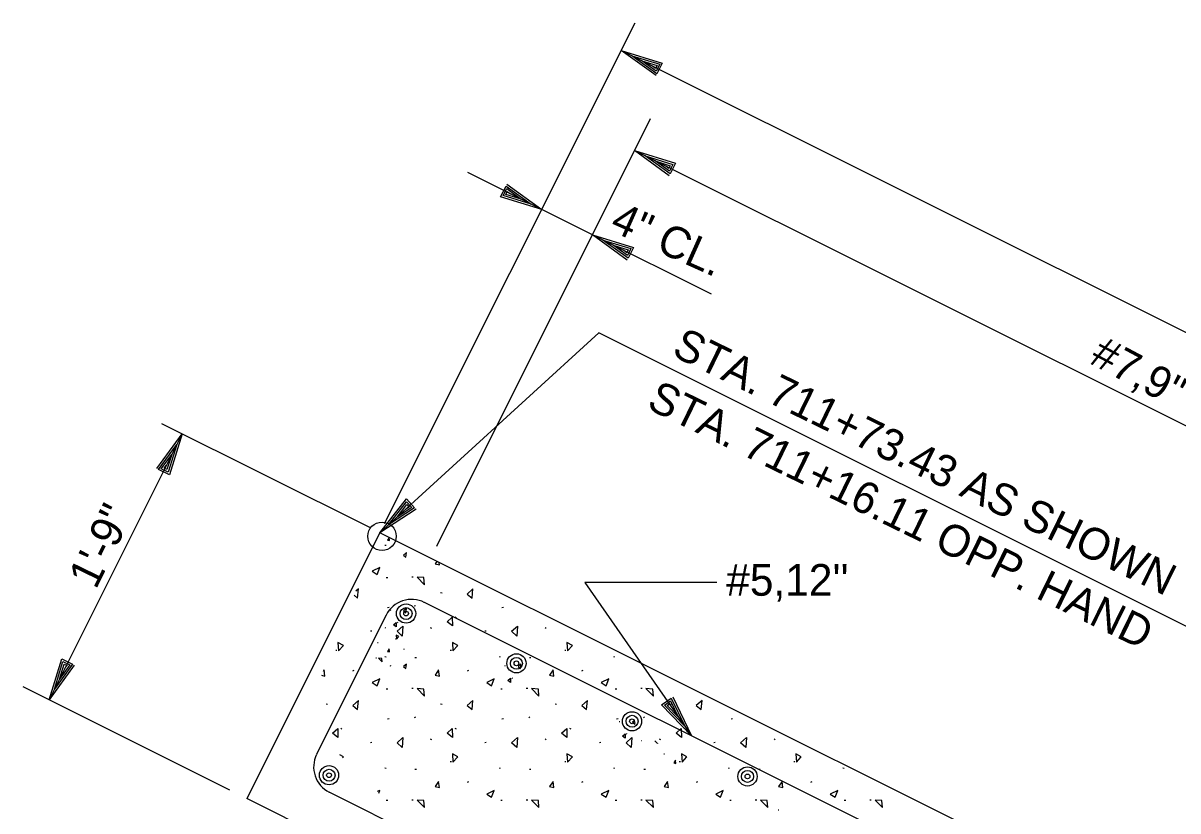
# Model space of a CAD drawing. Extents: x 6 to 106, y 3 to 74.
# Drawn here: x 75.56 to 89.14, y 35.93 to 45.2 of the extents above; entities that cross this region are included whole.
import ezdxf

# ---------------------------------------------------------------- set-up
doc = ezdxf.new("R2010")
doc.units = 0
for name, color, linetype in [('Level 22', 7, 'Continuous'), ('Level 3', 7, 'Continuous'), ('Level 44', 7, 'Continuous'), ('Level 50', 7, 'Continuous')]:
    doc.layers.add(name, color=color, linetype=linetype)

msp = doc.modelspace()

# ---------------------------------------------------------------- linework, layer by layer
at = {"layer": 'Level 22'}
for p, q in [((82.752, 45.203), (79.804, 39.308)), ((95.793, 38.28), (82.591, 44.881)), ((82.933, 44.075), (80.418, 39.043)), ((94.822, 37.665), (82.747, 43.702)), ((81.655, 43.009), (80.788, 43.443)), ((82.252, 42.711), (81.655, 43.009)), ((83.654, 42.01), (82.252, 42.711)), ((90.1, 37.67), (82.326, 41.557)), ((79.648, 39.257), (77.188, 40.487)), ((77.426, 40.368), (75.861, 37.237)), ((79.753, 39.204), (78.188, 36.074)), ((92.955, 32.603), (79.753, 39.204)), ((94.265, 31.389), (80.275, 38.384)), ((79.827, 38.235), (79.007, 36.596)), ((77.986, 36.175), (75.556, 37.39)), ((90.607, 30.423), (79.157, 36.148)), ((88.991, 30.672), (78.188, 36.074))]:
    msp.add_line(p, q, dxfattribs=at)
for centre, start, end in [((80.125, 38.086), 63.4343, 153.4357), ((79.306, 36.446), 153.4355, 243.4349)]:
    msp.add_arc(centre, 0.333, start, end, dxfattribs=at)
at = {"layer": 'Level 3'}
for p, q in [((83.337, 36.928), (83.337, 36.928)), ((83.416, 36.814), (83.416, 36.814))]:
    msp.add_line(p, q, dxfattribs=at)
for points in [[(83.715, 38.616), (82.163, 38.616), (83.416, 36.814)], [(83.199, 37.27), (83.416, 36.814), (83.063, 37.176), (83.18, 37.257), (83.337, 36.928), (83.098, 37.174), (83.172, 37.225), (83.261, 37.037), (83.132, 37.171), (83.162, 37.193), (83.182, 37.151)]]:
    msp.add_lwpolyline(points, dxfattribs=at)
at = {"layer": 'Level 44'}
for p, q in [((82.326, 41.557), (79.753, 39.204)), ((79.824, 39.052), (79.811, 39.054)), ((79.845, 38.674), (79.827, 38.674)), ((80.144, 38.68), (80.127, 38.68)), ((80.483, 38.494), (80.466, 38.497)), ((79.86, 38.325), (79.842, 38.32)), ((80.17, 38.343), (80.157, 38.338)), ((81.206, 38.325), (81.188, 38.32)), ((79.883, 38.289), (79.874, 38.291)), ((80.653, 38.201), (80.638, 38.21)), ((79.656, 38.045), (79.641, 38.044)), ((79.822, 38.081), (79.815, 38.084)), ((79.967, 38.143), (79.96, 38.148)), ((80.363, 38.077), (80.348, 38.084)), ((81.002, 38.045), (80.988, 38.044)), ((81.709, 38.077), (81.695, 38.084)), ((79.732, 37.907), (79.723, 37.907)), ((79.937, 37.952), (79.931, 37.952)), ((79.246, 37.818), (79.233, 37.819)), ((80.038, 37.834), (80.03, 37.83)), ((80.593, 37.818), (80.58, 37.819)), ((81.94, 37.818), (81.926, 37.819)), ((79.713, 37.727), (79.704, 37.727)), ((79.824, 37.74), (79.811, 37.743)), ((79.883, 37.633), (79.874, 37.635)), ((80.183, 37.729), (80.165, 37.729)), ((81.171, 37.74), (81.157, 37.743)), ((81.229, 37.633), (81.221, 37.635)), ((81.529, 37.729), (81.511, 37.729)), ((82.517, 37.74), (82.504, 37.743)), ((79.447, 37.583), (79.431, 37.575)), ((80.793, 37.583), (80.777, 37.575)), ((81.314, 37.487), (81.307, 37.492)), ((82.14, 37.583), (82.124, 37.575)), ((79.845, 37.362), (79.827, 37.362)), ((80.144, 37.368), (80.127, 37.368)), ((81.192, 37.362), (81.174, 37.362)), ((81.491, 37.368), (81.474, 37.368)), ((82.539, 37.362), (82.521, 37.362)), ((82.837, 37.368), (82.82, 37.368)), ((79.137, 37.182), (79.119, 37.185)), ((80.483, 37.182), (80.466, 37.185)), ((81.83, 37.182), (81.813, 37.185)), ((83.177, 37.182), (83.159, 37.185)), ((79.86, 37.013), (79.842, 37.008)), ((80.17, 37.031), (80.157, 37.026)), ((81.206, 37.013), (81.188, 37.008)), ((81.517, 37.031), (81.504, 37.026)), ((82.553, 37.013), (82.535, 37.008)), ((82.576, 36.978), (82.567, 36.979)), ((82.864, 37.031), (82.851, 37.026)), ((83.9, 37.013), (83.882, 37.008)), ((79.306, 36.89), (79.291, 36.899)), ((80.653, 36.89), (80.638, 36.899)), ((82, 36.89), (81.985, 36.899)), ((82.661, 36.831), (82.653, 36.836)), ((83.346, 36.89), (83.331, 36.899)), ((79.656, 36.734), (79.641, 36.732)), ((80.363, 36.766), (80.348, 36.772)), ((81.002, 36.734), (80.988, 36.732)), ((81.709, 36.766), (81.695, 36.772)), ((82.349, 36.734), (82.334, 36.732)), ((82.835, 36.753), (82.828, 36.753)), ((83.056, 36.766), (83.042, 36.772)), ((83.696, 36.734), (83.681, 36.732)), ((84.403, 36.766), (84.388, 36.772)), ((83.099, 36.595), (83.09, 36.595)), ((79.824, 36.429), (79.811, 36.431)), ((80.183, 36.417), (80.165, 36.417)), ((80.593, 36.507), (80.58, 36.508)), ((81.171, 36.429), (81.157, 36.431)), ((81.529, 36.417), (81.511, 36.417)), ((81.94, 36.507), (81.926, 36.508)), ((82.517, 36.429), (82.504, 36.431)), ((82.876, 36.417), (82.858, 36.417)), ((83.286, 36.507), (83.273, 36.508)), ((83.864, 36.429), (83.851, 36.431)), ((84.223, 36.417), (84.205, 36.417)), ((84.633, 36.507), (84.62, 36.508)), ((85.211, 36.429), (85.197, 36.431)), ((80.793, 36.272), (80.777, 36.264)), ((82.14, 36.272), (82.124, 36.264)), ((83.487, 36.272), (83.471, 36.264)), ((84.833, 36.272), (84.817, 36.264)), ((79.845, 36.05), (79.827, 36.05)), ((80.144, 36.057), (80.127, 36.057)), ((81.192, 36.05), (81.174, 36.05)), ((81.491, 36.057), (81.474, 36.057)), ((82.539, 36.05), (82.521, 36.05)), ((82.837, 36.057), (82.82, 36.057)), ((83.885, 36.05), (83.867, 36.05)), ((84.184, 36.057), (84.167, 36.057)), ((85.232, 36.05), (85.214, 36.05)), ((85.531, 36.057), (85.514, 36.057)), ((84.446, 35.939), (84.437, 35.939))]:
    msp.add_line(p, q, dxfattribs=at)
for points in [[(79.856, 39.138), (79.842, 39.118), (79.867, 39.112)], [(79.867, 39.112), (79.864, 39.133)], [(80.42, 38.866), (80.402, 38.839), (80.452, 38.827)], [(80.452, 38.827), (80.449, 38.851)], [(79.451, 38.467), (79.489, 38.434), (79.501, 38.542)], [(79.501, 38.542), (79.471, 38.515)], [(79.065, 37.525), (79.105, 37.516)], [(79.105, 37.516), (79.096, 37.589), (79.083, 37.569)], [(82.738, 36.984), (82.724, 36.972), (82.752, 36.948), (82.754, 36.969)], [(83.016, 36.724), (82.985, 36.753), (82.985, 36.753)], [(83.016, 36.725), (83.016, 36.724)], [(79.314, 36.556), (79.323, 36.566), (79.282, 36.588)], [(79.738, 36.138), (79.751, 36.171), (79.72, 36.156)]]:
    msp.add_lwpolyline(points, dxfattribs=at)
for points in [[(80.065, 38.969), (80.03, 38.939), (80.059, 38.915)], [(79.719, 38.713), (79.751, 38.794), (79.663, 38.751)], [(80.269, 38.676), (80.189, 38.68), (80.276, 38.591)], [(80.847, 38.542), (80.779, 38.482), (80.836, 38.434)], [(80.065, 38.313), (80.03, 38.283), (80.059, 38.26)], [(80.606, 38.107), (80.542, 38.155), (80.603, 38.21)], [(79.944, 38.096), (79.912, 38.12), (79.942, 38.147)], [(80.016, 37.987), (79.954, 38.044), (80.023, 38.105)], [(81.363, 37.987), (81.301, 38.044), (81.369, 38.105)], [(79.266, 37.814), (79.323, 37.878), (79.259, 37.912)], [(79.947, 37.949), (79.976, 37.981), (79.944, 37.998)], [(80.612, 37.814), (80.669, 37.878), (80.606, 37.912)], [(81.959, 37.814), (82.016, 37.878), (81.952, 37.912)], [(79.867, 37.8), (79.862, 37.837), (79.842, 37.806)], [(79.775, 37.724), (79.735, 37.727), (79.779, 37.682)], [(80.065, 37.657), (80.03, 37.628), (80.059, 37.604)], [(81.411, 37.657), (81.377, 37.628), (81.405, 37.604)], [(80.452, 37.516), (80.443, 37.589), (80.402, 37.528)], [(81.29, 37.44), (81.258, 37.464), (81.289, 37.491)], [(81.799, 37.516), (81.789, 37.589), (81.748, 37.528)], [(79.719, 37.401), (79.751, 37.483), (79.663, 37.44)], [(80.269, 37.364), (80.189, 37.368), (80.276, 37.28)], [(81.066, 37.401), (81.098, 37.483), (81.009, 37.44)], [(81.616, 37.364), (81.536, 37.368), (81.622, 37.28)], [(82.413, 37.401), (82.444, 37.483), (82.356, 37.44)], [(82.962, 37.364), (82.882, 37.368), (82.969, 37.28)], [(79.501, 37.23), (79.432, 37.17), (79.489, 37.123)], [(80.847, 37.23), (80.779, 37.17), (80.836, 37.123)], [(82.194, 37.23), (82.126, 37.17), (82.182, 37.123)], [(83.541, 37.23), (83.472, 37.17), (83.529, 37.123)], [(79.259, 36.795), (79.195, 36.844), (79.256, 36.898)], [(80.606, 36.795), (80.542, 36.844), (80.603, 36.898)], [(81.952, 36.795), (81.888, 36.844), (81.95, 36.898)], [(82.637, 36.784), (82.605, 36.808), (82.636, 36.836)], [(83.299, 36.795), (83.235, 36.844), (83.296, 36.898)], [(80.016, 36.675), (79.954, 36.732), (80.023, 36.793)], [(81.363, 36.675), (81.301, 36.732), (81.369, 36.793)], [(82.709, 36.675), (82.648, 36.732), (82.716, 36.793)], [(84.056, 36.675), (83.994, 36.732), (84.063, 36.793)], [(80.612, 36.502), (80.669, 36.566), (80.606, 36.6)], [(81.959, 36.502), (82.016, 36.566), (81.952, 36.6)], [(83.306, 36.502), (83.363, 36.566), (83.299, 36.6)], [(84.652, 36.502), (84.709, 36.566), (84.646, 36.6)], [(83.234, 36.489), (83.229, 36.525), (83.208, 36.495)], [(80.452, 36.204), (80.443, 36.277), (80.402, 36.216)], [(81.799, 36.204), (81.789, 36.277), (81.748, 36.216)], [(83.145, 36.204), (83.136, 36.277), (83.095, 36.216)], [(84.492, 36.204), (84.483, 36.277), (84.442, 36.216)], [(81.066, 36.089), (81.098, 36.171), (81.009, 36.128)], [(82.413, 36.089), (82.444, 36.171), (82.356, 36.128)], [(83.759, 36.089), (83.791, 36.171), (83.703, 36.128)], [(85.106, 36.089), (85.138, 36.171), (85.049, 36.128)], [(80.269, 36.052), (80.189, 36.057), (80.276, 35.968)], [(81.616, 36.052), (81.536, 36.057), (81.622, 35.968)], [(82.962, 36.052), (82.882, 36.057), (82.969, 35.968)], [(84.309, 36.052), (84.229, 36.057), (84.316, 35.968)], [(85.656, 36.052), (85.576, 36.057), (85.662, 35.968)]]:
    msp.add_lwpolyline(points, close=True, dxfattribs=at)
msp.add_circle((79.777, 39.162), 0.167, dxfattribs=at)
at = {"layer": 'Level 50'}
for p, q in [((82.591, 44.881), (82.591, 44.881)), ((82.715, 44.819), (82.715, 44.819)), ((82.747, 43.702), (82.747, 43.702)), ((82.871, 43.64), (82.871, 43.64)), ((81.531, 43.071), (81.531, 43.071)), ((81.655, 43.009), (81.655, 43.009)), ((82.252, 42.711), (82.252, 42.711)), ((82.376, 42.649), (82.376, 42.649)), ((77.426, 40.368), (77.426, 40.368)), ((77.364, 40.244), (77.364, 40.244)), ((79.855, 39.298), (79.855, 39.298)), ((79.753, 39.204), (79.753, 39.204)), ((75.923, 37.361), (75.923, 37.361)), ((75.861, 37.237), (75.861, 37.237))]:
    msp.add_line(p, q, dxfattribs=at)
for points in [[(83, 44.584), (82.591, 44.881), (83.074, 44.732), (83.011, 44.606), (82.715, 44.819), (83.043, 44.718), (83.003, 44.637), (82.834, 44.759), (83.012, 44.703), (82.995, 44.67), (82.958, 44.697)], [(83.156, 43.405), (82.747, 43.702), (83.23, 43.553), (83.167, 43.427), (82.871, 43.64), (83.199, 43.539), (83.158, 43.458), (82.99, 43.58), (83.168, 43.524), (83.151, 43.491), (83.114, 43.518)], [(81.246, 43.306), (81.655, 43.009), (81.172, 43.158), (81.236, 43.285), (81.531, 43.071), (81.203, 43.173), (81.244, 43.254), (81.412, 43.131), (81.234, 43.187), (81.251, 43.22), (81.288, 43.193)], [(82.661, 42.414), (82.252, 42.711), (82.735, 42.562), (82.671, 42.436), (82.376, 42.649), (82.704, 42.548), (82.663, 42.467), (82.495, 42.59), (82.673, 42.534), (82.656, 42.5), (82.619, 42.528)], [(77.129, 39.959), (77.426, 40.368), (77.277, 39.885), (77.15, 39.948), (77.364, 40.244), (77.262, 39.916), (77.181, 39.956), (77.304, 40.124), (77.248, 39.947), (77.215, 39.963), (77.242, 40)], [(80.177, 39.48), (79.753, 39.204), (80.065, 39.602), (80.16, 39.498), (79.855, 39.298), (80.067, 39.568), (80.128, 39.501), (79.954, 39.388), (80.07, 39.534), (80.095, 39.506), (80.056, 39.481)], [(76.158, 37.646), (75.861, 37.237), (76.01, 37.72), (76.136, 37.657), (75.923, 37.361), (76.024, 37.689), (76.105, 37.649), (75.982, 37.481), (76.038, 37.658), (76.072, 37.642), (76.044, 37.605)]]:
    msp.add_lwpolyline(points, dxfattribs=at)
for centre, radius in [((80.06, 38.252), 0.113), ((80.06, 38.252), 0.0703), ((80.06, 38.252), 0.0281), ((81.358, 37.666), 0.113), ((81.358, 37.666), 0.0703), ((81.358, 37.666), 0.0281), ((82.718, 36.984), 0.113), ((82.718, 36.984), 0.0703), ((82.718, 36.984), 0.0281), ((79.154, 36.349), 0.113), ((79.154, 36.349), 0.0703), ((84.076, 36.335), 0.113), ((84.076, 36.335), 0.0703), ((79.154, 36.349), 0.0281), ((84.076, 36.335), 0.0281)]:
    msp.add_circle(centre, radius, dxfattribs=at)

# ---------------------------------------------------------------- texts
at = {"layer": 'Level 22'}
for s, height, rotation, p in [('4" CL.', 0.3733, 336, (82.442, 42.767)), ('STA. 711+73.43 AS SHOWN', 0.37333, 334, (83.171, 41.296)), ('#7,9" E.F.', 0.3733, 332, (88.084, 41.204)), ('STA. 711+16.11 OPP. HAND', 0.37333, 334, (82.875, 40.674)), ('1\'-9"', 0.3733, 64, (76.411, 38.526))]:
    msp.add_text(s, height=height, rotation=rotation, dxfattribs=at).set_placement(p)
msp.add_text("#5,12''", height=0.3733, dxfattribs=at).set_placement((83.826, 38.462))

doc.saveas('drawing.dxf')
